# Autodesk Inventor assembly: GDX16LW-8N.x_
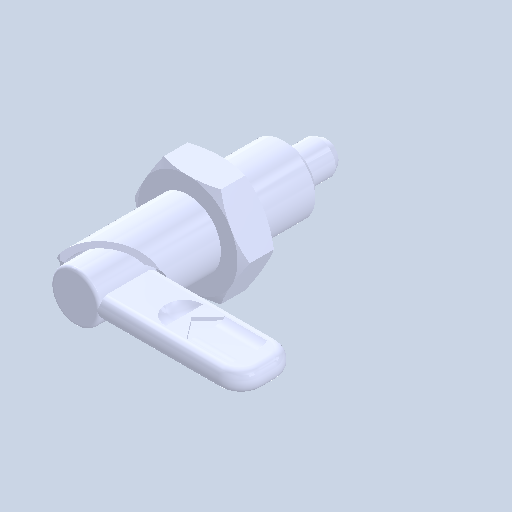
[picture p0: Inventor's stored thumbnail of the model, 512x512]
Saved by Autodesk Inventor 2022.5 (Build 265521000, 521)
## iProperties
Created: 2024-06
Part Number: GDX16LW-8N.x_
Document SubType Name: Assembly
Designer: ImaoCorp
Author: ImaoCorp
Sending System: SOLIDWORKS 2022-2022290
MC: AMD64
MC_MODEL: Intel64 Family 6 Model 60 Stepping 3, GenuineIntel
OS: Windows_NT
FRU: Parasolid Version 33.1, build 260,  4-25-2022
FORMAT: text
GUISE: transmit
KEY: FILEGDX16LW-8N.x_t
DATE: Wed Jun 12 09:32:38 2024
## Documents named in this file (4)
- Y:\5.更新分\2024年対応\xxxx_GDX\データ_imao品番\gdx16lw-8n\GDX16LW-8N.x_.iam
- Y:\5.更新分\2024年対応\xxxx_GDX\データ_imao品番\gdx16lw-8n\GDX16LW-8N_01.ipt
- Y:\5.更新分\2024年対応\xxxx_GDX\データ_imao品番\gdx16lw-8n\GDX16LW-8N_02.ipt
- Y:\5.更新分\2024年対応\xxxx_GDX\データ_imao品番\gdx16lw-8n\GDX16LW-8N_03.ipt
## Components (3 placed, 3 different names)
1. GDX16LW-8N_01
2. GDX16LW-8N_02
3. GDX16LW-8N_03
